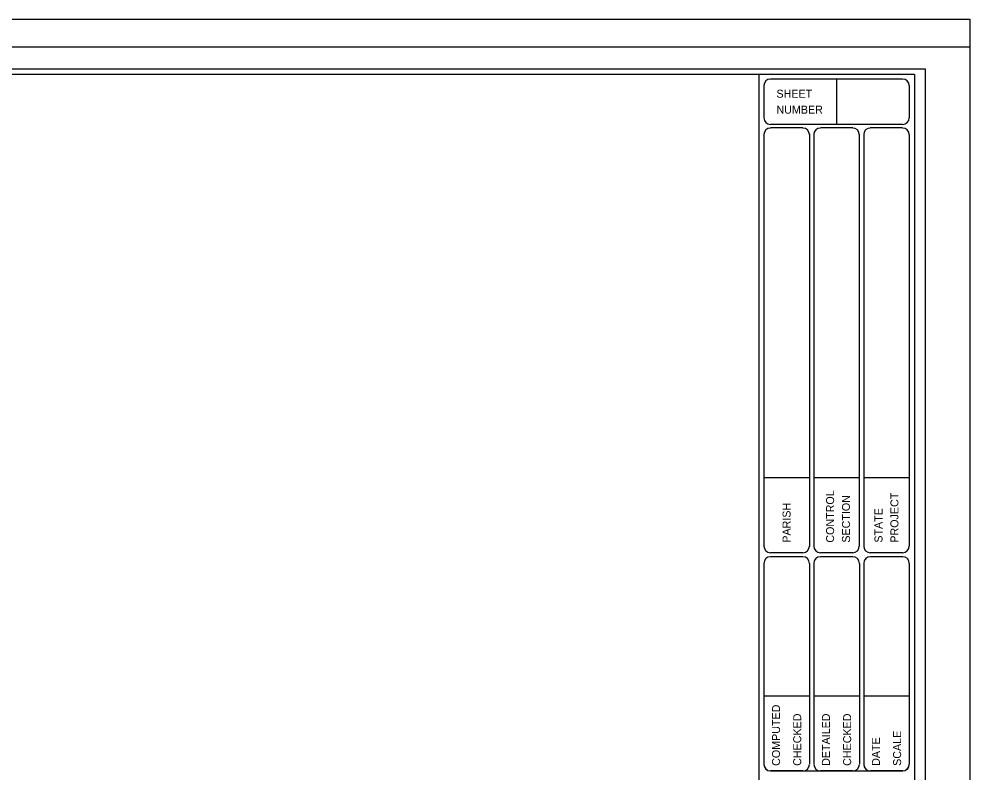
# Model space of a CAD drawing. Extents: x -0.21 to 2.64, y -0.06 to 1.81.
# Drawn here: x 1.929 to 2.642, y 1.226 to 1.792 of the extents above; entities that cross this region are included whole.
import ezdxf

# ---------------------------------------------------------------- set-up
doc = ezdxf.new("R2010")
doc.units = 0
for name, color, linetype in [('Plot Border', 7, 'Continuous'), ('Plot Border 2', 7, 'Continuous'), ('Sheet Border', 7, 'Continuous')]:
    doc.layers.add(name, color=color, linetype=linetype)

msp = doc.modelspace()

# ---------------------------------------------------------------- linework, layer by layer
at = {"layer": 'Plot Border'}
for points in [[(-0.19167, 1.79167), (2.64167, 1.79167), (2.64167, -0.04167), (-0.19167, -0.04167)], [(2.60833, 1.75417), (-0.14167, 1.75417), (-0.14167, -0.00417), (2.60833, -0.00417)]]:
    msp.add_lwpolyline(points, close=True, dxfattribs=at)
at = {"layer": 'Plot Border 2'}
msp.add_lwpolyline([(-0.19167, 1.77083), (2.64167, 1.77083), (2.64167, -0.02083), (-0.19167, -0.02083)], close=True, dxfattribs=at)
at = {"layer": 'Sheet Border'}
for p, q in [((2.6, 1.75), (-0.025, 1.75)), ((2.48333, 1.75), (2.48333, 0.02183)), ((2.5912, 1.7467), (2.49214, 1.7467)), ((2.54167, 1.7467), (2.54167, 1.71261)), ((2.6, 1.75), (2.6, 0)), ((2.48719, 1.74175), (2.48719, 1.71756)), ((2.59615, 1.74175), (2.59615, 1.71756)), ((2.5912, 1.71261), (2.49214, 1.71261)), ((2.48719, 1.70534), (2.48719, 1.3962)), ((2.51633, 1.70997), (2.49214, 1.70997)), ((2.52128, 1.70538), (2.52128, 1.39616)), ((2.52458, 1.70501), (2.52458, 1.39657)), ((2.55376, 1.70997), (2.52953, 1.70997)), ((2.55871, 1.70505), (2.55871, 1.39649)), ((2.56202, 1.70501), (2.56202, 1.39657)), ((2.5912, 1.70997), (2.56697, 1.70997)), ((2.59615, 1.70501), (2.59615, 1.39657)), ((2.52128, 1.44775), (2.48719, 1.44775)), ((2.55871, 1.44775), (2.52458, 1.44775)), ((2.59615, 1.44775), (2.56202, 1.44775)), ((2.51633, 1.39162), (2.49214, 1.39162)), ((2.55376, 1.39162), (2.52953, 1.39162)), ((2.5912, 1.39162), (2.56697, 1.39162)), ((2.48719, 1.38399), (2.48719, 1.23297)), ((2.51637, 1.38857), (2.49214, 1.38857)), ((2.52132, 1.38361), (2.52132, 1.23297)), ((2.52462, 1.38399), (2.52462, 1.23297)), ((2.5538, 1.38857), (2.52958, 1.38857)), ((2.55876, 1.38361), (2.55876, 1.23297)), ((2.56206, 1.38399), (2.56206, 1.23297)), ((2.59124, 1.38857), (2.56701, 1.38857)), ((2.59619, 1.38361), (2.59619, 1.23297)), ((2.52128, 1.28414), (2.48719, 1.28414)), ((2.55871, 1.28414), (2.52458, 1.28414)), ((2.59615, 1.28414), (2.56202, 1.28414)), ((2.49214, 1.22804), (2.5912, 1.22804)), ((2.51637, 1.22801), (2.49214, 1.22801)), ((2.5538, 1.22801), (2.52958, 1.22801)), ((2.59124, 1.22801), (2.56701, 1.22801))]:
    msp.add_line(p, q, dxfattribs=at)
for centre, start, end in [((2.49213, 1.74175), 90, 180), ((2.59118, 1.74175), 0, 90), ((2.49213, 1.71754), 180, 270), ((2.59118, 1.71754), 270, 0), ((2.49213, 1.70499), 90, 180), ((2.51634, 1.70499), 0, 90), ((2.52955, 1.70499), 90, 180), ((2.55376, 1.70499), 0, 90), ((2.56697, 1.70499), 90, 180), ((2.59118, 1.70499), 0, 90), ((2.49213, 1.39656), 180, 270), ((2.51634, 1.39656), 270, 0), ((2.52955, 1.39656), 180, 270), ((2.55376, 1.39656), 270, 0), ((2.56697, 1.39656), 180, 270), ((2.59118, 1.39656), 270, 0), ((2.49213, 1.38363), 90, 180), ((2.51635, 1.38363), 0, 90), ((2.52956, 1.38363), 90, 180), ((2.55379, 1.38363), 0, 90), ((2.567, 1.38363), 90, 180), ((2.59122, 1.38363), 0, 90), ((2.49213, 1.233), 180, 270), ((2.49214, 1.23295), 180, 270), ((2.51635, 1.23295), 270, 0), ((2.52958, 1.23295), 180, 270), ((2.55379, 1.23295), 270, 0), ((2.56701, 1.23295), 180, 270), ((2.59118, 1.233), 270, 0), ((2.59122, 1.23295), 270, 0)]:
    msp.add_arc(centre, 0.00495, start, end, dxfattribs=at)

# ---------------------------------------------------------------- texts
for s, p in [('SHEET', (2.49664, 1.73266)), ('NUMBER', (2.49664, 1.72073))]:
    msp.add_text(s, height=0.006, dxfattribs=at).set_placement(p)
for s, p in [('CONTROL', (2.53982, 1.39913)), ('SECTION', (2.55175, 1.39913)), ('PROJECT', (2.58803, 1.39913)), ('PARISH', (2.50721, 1.39913)), ('STATE', (2.5761, 1.39913)), ('COMPUTED', (2.49929, 1.23182)), ('CHECKED', (2.51518, 1.23182)), ('DETAILED', (2.53672, 1.23182)), ('CHECKED', (2.55261, 1.23182)), ('SCALE', (2.59005, 1.23182)), ('DATE', (2.57416, 1.23182))]:
    msp.add_text(s, height=0.006, rotation=90, dxfattribs=at).set_placement(p)

doc.saveas('drawing.dxf')
